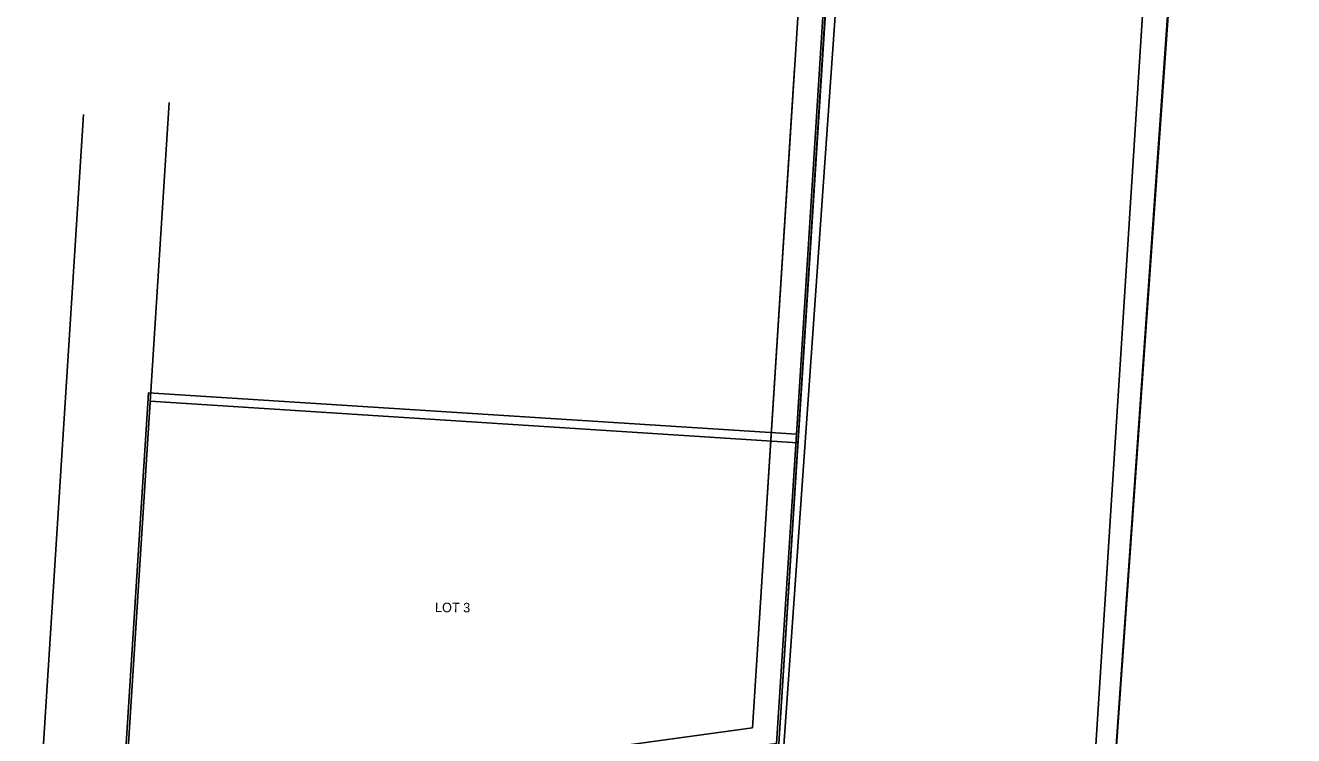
# Model space of a CAD drawing. Extents: x 1532954 to 1577849, y 698998 to 706606.
# Drawn here: x 1573832.2 to 1574206.2, y 703438.2 to 703647.6 of the extents above; entities that cross this region are included whole.
import ezdxf

# ---------------------------------------------------------------- set-up
doc = ezdxf.new("R2010")
doc.units = 0
for name, color, linetype in [('DV_X_Property_Line', 7, 'Continuous'), ('RW_X_CL', 7, 'Continuous'), ('RW_X_Esmt_U', 7, 'Continuous'), ('RW_X_Fee_RW', 7, 'Continuous'), ('SC_Scratch1', 7, 'Continuous'), ('SC_Scratch2', 7, 'Continuous'), ('SC_Scratch3', 7, 'Continuous')]:
    doc.layers.add(name, color=color, linetype=linetype)

msp = doc.modelspace()

# ---------------------------------------------------------------- linework, layer by layer
at = {"layer": 'DV_X_Property_Line'}
for p, q in [((1574136.48, 703186.47), (1574188.16, 703924.56)), ((1574037.66, 703173), (1574084.63, 703911.12)), ((1573869.01, 703536.77), (1574060.03, 703524.49))]:
    msp.add_line(p, q, dxfattribs=at)
at = {"layer": 'RW_X_CL'}
msp.add_line((1573818.91, 703143.18), (1573849.35, 703621.38), dxfattribs=at)
at = {"layer": 'RW_X_Esmt_U'}
for p, q in [((1574046.66, 703440.44), (1574059.04, 703634.91)), ((1573861.27, 703415.17), (1574046.66, 703440.44))]:
    msp.add_line(p, q, dxfattribs=at)
at = {"layer": 'RW_X_Fee_RW'}
msp.add_line((1573846.78, 703187.35), (1573874.62, 703624.83), dxfattribs=at)
at = {"layer": 'SC_Scratch1'}
msp.add_lwpolyline([(1574623.21, 704615.75), (1574580.13, 703940.99), (1574479.08, 703927.65), (1574283.38, 703901.81), (1574176.78, 703887.73), (1574134.84, 703230.69), (1574132.24, 703189.96), (1574047.81, 703178.38), (1574037.25, 703176.93), (1574039.84, 703217.66), (1574053.75, 703435.89), (1574059.56, 703527.11), (1574066.62, 703637.88), (1574073.68, 703748.66), (1574080.74, 703859.43), (1574081.75, 703875.18), (1574087.8, 703970.21), (1574094.86, 704080.98), (1574101.92, 704191.76)], dxfattribs=at)
msp.add_lwpolyline([(1574059.56, 703527.11), (1574059.56, 703527.11), (1574053.75, 703435.89), (1573957.01, 703422.72), (1573860.27, 703409.54), (1573868.54, 703539.28)], close=True, dxfattribs=at)
at = {"layer": 'SC_Scratch2'}
for p, q in [((1574175.23, 705334.64), (1574037.66, 703173)), ((1574166.75, 705327.39), (1574046.66, 703440.44)), ((1573874.62, 703624.83), (1573846.78, 703187.35)), ((1573849.35, 703621.38), (1573818.91, 703143.18)), ((1573869.01, 703536.77), (1574060.03, 703524.49)), ((1574046.66, 703440.44), (1573861.27, 703415.17))]:
    msp.add_line(p, q, dxfattribs=at)
at = {"layer": 'SC_Scratch3'}
for p, q in [((1574136.47, 703186.42), (1574188.53, 703925.45)), ((1574037.38, 703172.96), (1574089.44, 703911.99))]:
    msp.add_line(p, q, dxfattribs=at)

# ---------------------------------------------------------------- texts
at = {"layer": 'SC_Scratch2'}
msp.add_text('LOT 3', height=2.8, rotation=359.4613, dxfattribs=at).set_placement((1573952.98, 703474.6))

doc.saveas('drawing.dxf')
